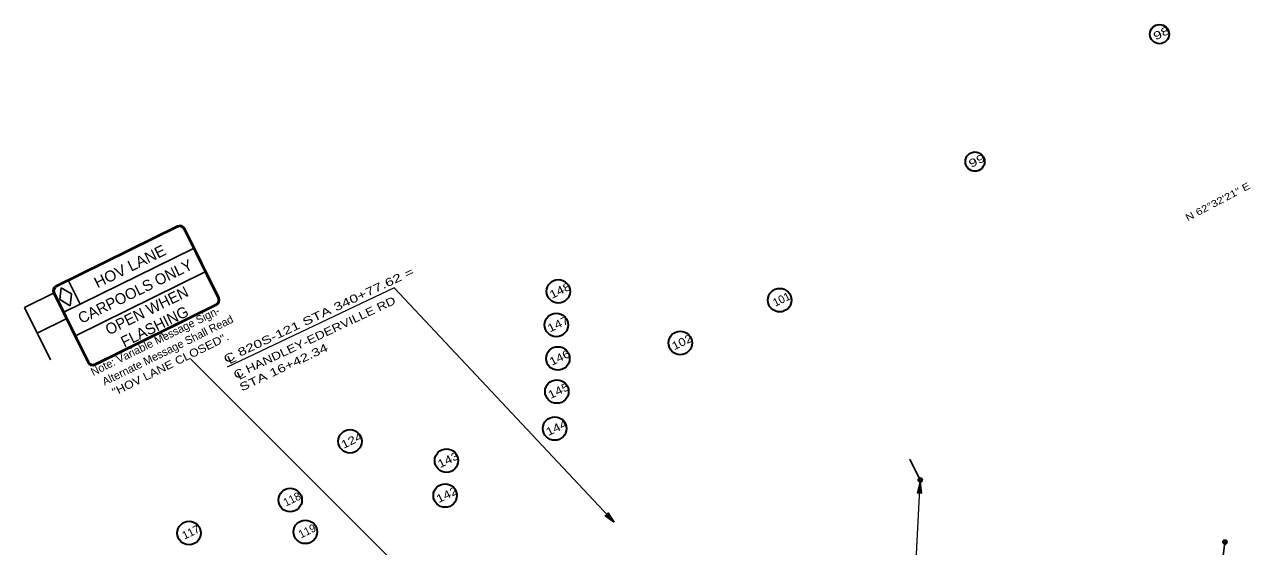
# Model space of a CAD drawing. Extents: x 2356431 to 2371438, y 6972864 to 6982525.
# Drawn here: x 2360660 to 2362804, y 6977631 to 6978545 of the extents above; entities that cross this region are included whole.
import ezdxf
from ezdxf.enums import TextEntityAlignment as Align

# ---------------------------------------------------------------- set-up
doc = ezdxf.new("R2010")
doc.units = 0
doc.header["$LTSCALE"] = 5.6
for name, color, linetype, lineweight in [('17', 7, 'Continuous', 35), ('28', 7, 'Continuous', 35), ('48', 7, 'Continuous', 25), ('61', 7, 'Continuous', 13)]:
    doc.layers.add(name, color=color, linetype=linetype, lineweight=lineweight)
doc.layers.add('25', color=7, linetype='Continuous')

msp = doc.modelspace()

# ---------------------------------------------------------------- hatches: boundary and pattern name
at = {"layer": '48'}
for points in [[(2362226.507, 6977743.821), (2362221.573, 6977724.918), (2362228.761, 6977724.424)], [(2362230.281, 6977747.51, 1), (2362222.818, 6977747.595, 1)], [(2361691.155, 6977673.757), (2361680.461, 6977690.113), (2361675.268, 6977685.126)], [(2362762.671, 6977636.736, 1), (2362756.501, 6977640.935, 1)]]:
    msp.add_hatch(color=256, dxfattribs=at).paths.add_polyline_path(points)

# ---------------------------------------------------------------- linework, layer by layer
at = {"layer": '17'}
for centre, radius in [((2362645.174, 6978528.128), 16.828), ((2362322.321, 6978304.964), 16.828), ((2361593.451, 6978077.847), 20.576), ((2361980.783, 6978062.433), 20.576), ((2361589.945, 6978019.063), 20.576), ((2361806.763, 6977987.557), 20.576), ((2361592.671, 6977960.403), 20.576), ((2361590.852, 6977902.452), 20.576), ((2361587.158, 6977837.672), 20.576), ((2361228.952, 6977815.325), 20.576), ((2361397.718, 6977781.557), 20.576), ((2361395.383, 6977720.4), 20.576), ((2361124.414, 6977712.58), 20.576), ((2360947.375, 6977654.716), 20.576), ((2361150.898, 6977656.793), 20.576)]:
    msp.add_circle(centre, radius, dxfattribs=at)
at = {"layer": '48'}
for p, q in [((2360714.531, 6978087.535), (2360927, 6978192.391)), ((2360716.392, 6978086.464), (2360926.71, 6978190.268)), ((2360939.801, 6978188.049), (2360974.988, 6978116.756)), ((2360999.842, 6978066.381), (2360939.801, 6978188.049)), ((2360997.705, 6978066.659), (2360938.726, 6978186.19)), ((2360728.645, 6978041.376), (2360955.046, 6978153.12)), ((2360748.934, 6978000.257), (2360975.34, 6978112.001)), ((2360721.565, 6978063.346), (2360723.891, 6978083.847)), ((2360723.891, 6978083.847), (2360741.577, 6978073.22)), ((2360736.706, 6978096.492), (2360757.001, 6978055.371)), ((2360659.579, 6978049.748), (2360710.189, 6978074.726)), ((2360710.189, 6978074.726), (2360770.231, 6977953.054)), ((2360712.325, 6978074.448), (2360771.31, 6977954.919)), ((2360721.565, 6978063.346), (2360739.253, 6978052.719)), ((2360739.253, 6978052.719), (2360741.577, 6978073.22)), ((2360659.579, 6978049.748), (2360704.915, 6977957.887)), ((2360995.502, 6978053.58), (2360783.04, 6977948.711)), ((2360993.632, 6978054.657), (2360783.317, 6977950.852)), ((2360681.709, 6978004.91), (2360732.316, 6978029.888)), ((2362208.506, 6977784.138), (2362226.55, 6977747.553)), ((2362759.58, 6977638.842), (2362749.046, 6977556.87))]:
    msp.add_line(p, q, dxfattribs=at)
at = {"layer": '48', "lineweight": 13}
for p, q in [((2361306.403, 6978084.124), (2361014.281, 6977945.058)), ((2361691.155, 6977673.757), (2361306.403, 6978084.124)), ((2360898.094, 6978005.5), (2360903.519, 6978000.078)), ((2360950.551, 6977959.272), (2361426.415, 6977483.624)), ((2362205.326, 6977319.927), (2362226.507, 6977743.821))]:
    msp.add_line(p, q, dxfattribs=at)
at = {"layer": '48'}
for points in [[(2362226.507, 6977743.821), (2362221.573, 6977724.918), (2362228.761, 6977724.424)], [(2361691.155, 6977673.757), (2361680.461, 6977690.113), (2361675.268, 6977685.126)]]:
    msp.add_lwpolyline(points, close=True, dxfattribs=at)
for centre in [(2362226.55, 6977747.553), (2362759.586, 6977638.836)]:
    msp.add_circle(centre, 3.732, dxfattribs=at)
for centre, radius, start, end in [((2360930.686, 6978182.213), 8.966, 26.26515, 116.26515), ((2360931.229, 6978183.814), 9.563, 26.26515, 116.26515), ((2360718.763, 6978078.958), 9.563, 116.26456, 206.26456), ((2360720.364, 6978078.415), 8.966, 116.26456, 206.26456), ((2360989.665, 6978062.692), 8.966, 296.26515, 26.26515), ((2360991.266, 6978062.149), 9.563, 296.26515, 26.26515), ((2360778.807, 6977957.286), 9.563, 206.26456, 296.26456), ((2360779.35, 6977958.887), 8.966, 206.26456, 296.26456)]:
    msp.add_arc(centre, radius, start, end, dxfattribs=at)

# ---------------------------------------------------------------- texts
at = {"layer": '17'}
for s, width, p in [('98', 1.4, (2362651.47, 6978523.428)), ('99', 1.4, (2362328.615, 6978300.265)), ('148', 1.25, (2361599.646, 6978073.098)), ('147', 1.25, (2361596.141, 6978014.315)), ('102', 1.2, (2361813.009, 6977982.832)), ('146', 1.2, (2361598.867, 6977955.654)), ('145', 1.25, (2361597.047, 6977897.703)), ('144', 1.25, (2361593.353, 6977832.923)), ('124', 1.25, (2361235.147, 6977810.576)), ('143', 1.25, (2361403.913, 6977776.808)), ('142', 1.25, (2361401.578, 6977715.651))]:
    msp.add_text(s, height=14, rotation=26.268, dxfattribs=dict(at, width=width)).set_placement(p, align=Align.CENTER)
for s, p in [('101', (2361986.979, 6978057.685)), ('118', (2361130.61, 6977707.831)), ('117', (2360953.57, 6977649.967)), ('119', (2361157.094, 6977652.044))]:
    msp.add_text(s, height=14, rotation=26.268, dxfattribs=at).set_placement(p, align=Align.CENTER)
at = {"layer": '25'}
for s, width, p in [('C 820S-121 STA 340+77.62 =', 1.45, (2361012.017, 6977951.808)), ('C HANDLEY-EDERVILLE RD', 1.25, (2361029.396, 6977924.24)), ('STA 16+42.34', 1.4, (2361039.642, 6977902.535)), ('L', 1.4, (2361018.321, 6977950.13)), ('L', 1.4, (2361034.867, 6977922.649))]:
    msp.add_text(s, height=14, rotation=25.268, dxfattribs=dict(at, width=width)).set_placement(p)
at = {"layer": '28', "width": 1.25}
msp.add_text('N 62°32\'21" E', height=12, rotation=27.784, dxfattribs=at).set_placement((2362749.804, 6978229.515), align=Align.CENTER)
at = {"layer": '48', "width": 1.05}
msp.add_text('HOV LANE', height=19.13, rotation=26.264, dxfattribs=at).set_placement((2360848.074, 6978113), align=Align.CENTER)
at = {"layer": '48'}
for s, p in [('CARPOOLS ONLY', (2360857.319, 6978069.196)), ('OPEN WHEN', (2360877.69, 6978035.582)), ('FLASHING', (2360891.463, 6978007.67))]:
    msp.add_text(s, height=19.13, rotation=26.264, dxfattribs=at).set_placement(p, align=Align.CENTER)
at = {"layer": '61'}
for s, p in [('Note: Variable Message Sign-', (2360779.773, 6977929.365)), ('  Alternate Message Shall Read', (2360790.395, 6977907.842))]:
    msp.add_text(s, height=14, rotation=26.268, dxfattribs=at).set_placement(p)
at = {"layer": '61', "width": 1.15}
msp.add_text('   "HOV LANE CLOSED".', height=14, rotation=26.268, dxfattribs=at).set_placement((2360801.018, 6977886.32))

doc.saveas('drawing.dxf')
